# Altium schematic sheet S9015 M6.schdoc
size 127 x 101 mm
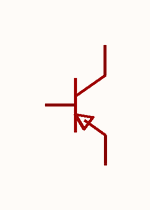
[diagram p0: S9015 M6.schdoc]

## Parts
Q?  s9015(range:300-400)  [SOT-23-3_L2.9-W1.3-P1.90-LS2.4-BR]  (value not drawn)

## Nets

Not connected (* = marked no-connect by the designer): Q? 1(B) 2(E) 3(C)

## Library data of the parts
Q? = s9015(range:300-400): 晶体管类型:PNP;集电极电流(Ic):100mA;集射极击穿电压(Vceo):45V;耗散功率(Pd):200mW;直流电流增益(hFE):200;; Manufacturer: CJ(江苏长电/长晶); Symbol: S9015 M6; AddInBom: yes; ModelId: c62791f0466c4ae2a892c056b845b0ca; ModelName: SOT-23-3P_L2.9-W1.3-H1.0-LS2.4-P0.95; ModelTransform: 98.425,114.173,0,180,0,0,0.0005,-0.0005,0; type: PNP; Current - Collector(Ic): 100mA; Collector - Emitter Voltage VCEO: 45V; Pd - Power Dissipation: 200mW; DC Current Gain: 200; Transition frequency(fT): 150MHz; Current - Collector Cutoff: 100nA; Vce Saturation(VCE(sat)): 300mV; Emitter-Base Voltage(Vebo): 5V; Number: 1个PNP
